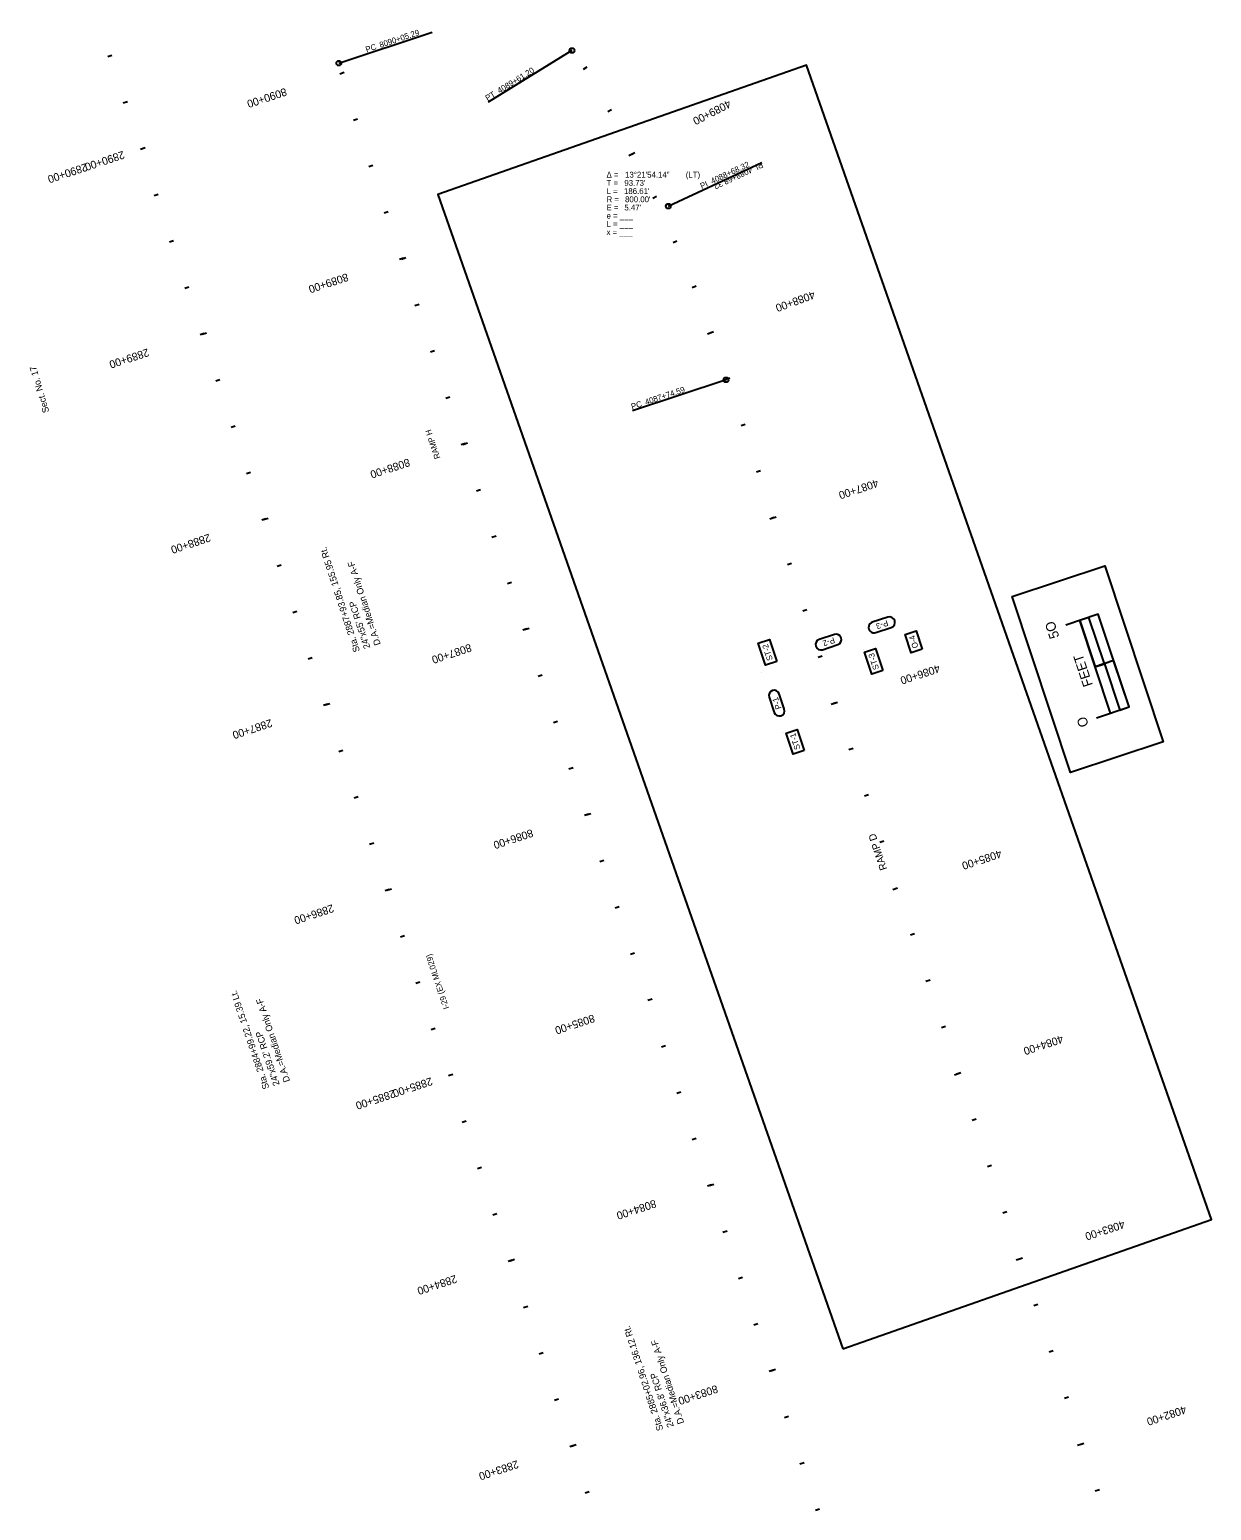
# Model space of a CAD drawing. Extents: x 16395645 to 16399055, y 7230557 to 7240583.
# Drawn here: x 16397055 to 16397660, y 7235571 to 7236330 of the extents above; entities that cross this region are included whole.
import ezdxf

# ---------------------------------------------------------------- set-up
doc = ezdxf.new("R2010")
doc.units = 0
for name, color, linetype in [('Default', 7, 'Continuous'), ('Dimensions', 7, 'Continuous'), ('NamedBoundary', 7, 'Continuous'), ('SheetText', 7, 'Continuous'), ('Text', 7, 'Continuous'), ('TextAlignment', 7, 'Continuous'), ('TextAlignmentLrg', 7, 'Continuous'), ('TextAlignmentSml', 7, 'Continuous')]:
    doc.layers.add(name, color=color, linetype=linetype)

msp = doc.modelspace()

# ---------------------------------------------------------------- linework, layer by layer
at = {"layer": 'Default'}
for p, q in [((16397481.85, 7236012.31), (16397481.85, 7236012.31)), ((16397429.88, 7236000.63), (16397429.88, 7236000.63)), ((16397440.65, 7235969.43), (16397440.65, 7235969.43))]:
    msp.add_line(p, q, dxfattribs=at)
at = {"layer": 'Dimensions'}
for p, q in [((16397494.46, 7236028.78), (16397486.54, 7236026.15)), ((16397467.16, 7236019.93), (16397459.32, 7236017.32)), ((16397488.29, 7236020.87), (16397496.21, 7236023.5)), ((16397461.06, 7236012.1), (16397468.9, 7236014.71)), ((16397441.47, 7235981.72), (16397438.9, 7235989.46)), ((16397433.72, 7235987.74), (16397436.29, 7235980))]:
    msp.add_line(p, q, dxfattribs=at)
for points in [[(16397512.09, 7236012.43), (16397506.4, 7236010.54), (16397503.31, 7236019.82), (16397509, 7236021.71)], [(16397437.57, 7236006.08), (16397431.88, 7236004.19), (16397428.14, 7236015.44), (16397433.83, 7236017.33)], [(16397491.93, 7236001.41), (16397486.23, 7235999.52), (16397482.48, 7236010.81), (16397488.18, 7236012.7)], [(16397451.65, 7235960.48), (16397445.96, 7235958.58), (16397442.39, 7235969.32), (16397448.09, 7235971.21)]]:
    msp.add_lwpolyline(points, close=True, dxfattribs=at)
for centre, radius, start, end in [((16397495.34, 7236026.14), 2.78, 288.38009, 108.38009), ((16397468.03, 7236017.32), 2.75, 288.38195, 108.38195), ((16397487.42, 7236023.51), 2.78, 108.38009, 288.38009), ((16397460.19, 7236014.71), 2.75, 108.38195, 288.38195), ((16397436.31, 7235988.6), 2.73, 18.38195, 198.38195), ((16397438.88, 7235980.86), 2.73, 198.38195, 18.38195)]:
    msp.add_arc(centre, radius, start, end, dxfattribs=at)
at = {"layer": 'NamedBoundary'}
msp.add_lwpolyline([(16397471.39, 7235654.1), (16397660.13, 7235720.26), (16397452.89, 7236311.41), (16397264.15, 7236245.24)], close=True, dxfattribs=at)
at = {"layer": 'SheetText'}
msp.add_line((16397610.1, 7236006.51), (16397600.61, 7236003.35), dxfattribs=at)
msp.add_line((16397610.1, 7236006.51), (16397600.61, 7236003.35), dxfattribs=at)
for points in [[(16397588.07, 7235949.13), (16397558.11, 7236039.28), (16397605.56, 7236055.05), (16397635.52, 7235964.9)], [(16397588.07, 7235949.13), (16397558.11, 7236039.28), (16397605.56, 7236055.05), (16397635.52, 7235964.9)], [(16397635.52, 7235964.9), (16397588.07, 7235949.13), (16397558.11, 7236039.28), (16397605.56, 7236055.05)], [(16397605.33, 7236004.92), (16397597.44, 7236028.64), (16397592.73, 7236027.08), (16397600.61, 7236003.35)], [(16397617.99, 7235982.78), (16397610.1, 7236006.51), (16397605.33, 7236004.92), (16397613.21, 7235981.19)]]:
    msp.add_lwpolyline(points, close=True, dxfattribs=at)
for points in [[(16397601.38, 7235977.26), (16397617.99, 7235982.78), (16397602.22, 7236030.23), (16397585.61, 7236024.71)], [(16397608.5, 7235979.63), (16397592.73, 7236027.08)]]:
    msp.add_lwpolyline(points, dxfattribs=at)
at = {"layer": 'TextAlignment'}
for p, q in [((16397213.38, 7236312.46), (16397261.21, 7236328.35)), ((16397261.21, 7236328.35), (16397261.21, 7236328.35)), ((16397332.76, 7236318.95), (16397289.9, 7236292.43)), ((16397289.9, 7236292.43), (16397289.9, 7236292.43)), ((16397382.08, 7236239.24), (16397429.9, 7236261.61)), ((16397382.08, 7236239.24), (16397429.9, 7236261.61)), ((16397429.9, 7236261.61), (16397429.9, 7236261.61)), ((16397429.9, 7236261.61), (16397429.9, 7236261.61)), ((16397411.63, 7236150.29), (16397363.81, 7236134.4)), ((16397363.81, 7236134.4), (16397363.81, 7236134.4))]:
    msp.add_line(p, q, dxfattribs=at)
for centre in [(16397332.76, 7236318.95), (16397213.38, 7236312.46), (16397382.08, 7236239.24), (16397382.08, 7236239.24), (16397411.63, 7236150.29)]:
    msp.add_circle(centre, 1.25, dxfattribs=at)
at = {"layer": 'TextAlignmentLrg'}
for p, q in [((16397213.88, 7236307.05), (16397216.21, 7236307.83)), ((16397111.84, 7236268.5), (16397114.16, 7236269.27)), ((16397362.94, 7236265.72), (16397364.88, 7236266.73)), ((16397246.58, 7236212.54), (16397244.51, 7236211.85)), ((16397144.53, 7236173.98), (16397142.46, 7236173.3)), ((16397403.24, 7236174.28), (16397405.29, 7236175.03)), ((16397278.12, 7236117.65), (16397276.04, 7236116.96)), ((16397435.16, 7236079.51), (16397437.23, 7236080.2)), ((16397176.07, 7236079.09), (16397174, 7236078.4)), ((16397309.65, 7236022.75), (16397307.58, 7236022.06)), ((16397207.6, 7235984.19), (16397205.53, 7235983.5)), ((16397466.69, 7235984.61), (16397468.76, 7235985.3)), ((16397341.19, 7235927.85), (16397339.11, 7235927.16)), ((16397497.06, 7235889.33), (16397499.39, 7235890.1)), ((16397239.14, 7235889.29), (16397237.07, 7235888.6)), ((16397371.56, 7235832.57), (16397373.88, 7235833.34)), ((16397269.51, 7235794.01), (16397271.83, 7235794.78)), ((16397529.76, 7235794.82), (16397531.83, 7235795.51)), ((16397404.26, 7235738.06), (16397402.18, 7235737.37)), ((16397561.3, 7235699.92), (16397563.37, 7235700.61)), ((16397302.21, 7235699.5), (16397300.14, 7235698.81)), ((16397435.79, 7235643.16), (16397433.72, 7235642.47)), ((16397333.74, 7235604.6), (16397331.67, 7235603.91)), ((16397592.83, 7235605.02), (16397594.9, 7235605.71))]:
    msp.add_line(p, q, dxfattribs=at)
at = {"layer": 'TextAlignmentSml'}
for p, q in [((16397097.23, 7236316.33), (16397095.16, 7236315.64)), ((16397213.88, 7236307.05), (16397216.21, 7236307.83)), ((16397338.58, 7236309.38), (16397340.46, 7236310.51)), ((16397105.11, 7236292.61), (16397103.04, 7236291.92)), ((16397351.1, 7236287.74), (16397353.01, 7236288.81)), ((16397222.93, 7236283.72), (16397220.86, 7236283.03)), ((16397111.84, 7236268.5), (16397114.16, 7236269.27)), ((16397361.85, 7236265.16), (16397364.02, 7236266.29)), ((16397230.81, 7236259.99), (16397228.74, 7236259.3)), ((16397120.88, 7236245.16), (16397118.81, 7236244.47)), ((16397374.08, 7236243.35), (16397376.05, 7236244.29)), ((16397238.7, 7236236.27), (16397236.62, 7236235.58)), ((16397128.77, 7236221.43), (16397126.69, 7236220.74)), ((16397384.52, 7236220.63), (16397386.52, 7236221.51)), ((16397245.42, 7236212.16), (16397247.74, 7236212.93)), ((16397136.65, 7236197.71), (16397134.58, 7236197.02)), ((16397394.24, 7236197.6), (16397396.27, 7236198.42)), ((16397254.46, 7236188.82), (16397252.39, 7236188.13)), ((16397143.37, 7236173.6), (16397145.69, 7236174.37)), ((16397402.09, 7236173.85), (16397404.39, 7236174.7)), ((16397262.35, 7236165.09), (16397260.28, 7236164.41)), ((16397152.42, 7236150.26), (16397150.34, 7236149.57)), ((16397411.5, 7236150.68), (16397413.58, 7236151.37)), ((16397270.23, 7236141.37), (16397268.16, 7236140.68)), ((16397160.3, 7236126.54), (16397158.23, 7236125.85)), ((16397419.39, 7236126.96), (16397421.46, 7236127.65)), ((16397276.95, 7236117.26), (16397279.28, 7236118.03)), ((16397168.18, 7236102.81), (16397166.11, 7236102.12)), ((16397427.27, 7236103.23), (16397429.34, 7236103.92)), ((16397286, 7236093.92), (16397283.93, 7236093.23)), ((16397174.91, 7236078.7), (16397177.23, 7236079.47)), ((16397433.99, 7236079.12), (16397436.32, 7236079.9)), ((16397293.88, 7236070.2), (16397291.81, 7236069.51)), ((16397183.95, 7236055.36), (16397181.88, 7236054.67)), ((16397443.04, 7236055.78), (16397445.11, 7236056.47)), ((16397301.77, 7236046.47), (16397299.69, 7236045.78)), ((16397191.84, 7236031.64), (16397189.76, 7236030.95)), ((16397450.92, 7236032.06), (16397453, 7236032.75)), ((16397308.49, 7236022.36), (16397310.81, 7236023.13)), ((16397199.72, 7236007.91), (16397197.65, 7236007.23)), ((16397458.81, 7236008.34), (16397460.88, 7236009.02)), ((16397317.53, 7235999.02), (16397315.46, 7235998.33)), ((16397206.44, 7235983.8), (16397208.76, 7235984.58)), ((16397465.53, 7235984.23), (16397467.85, 7235985)), ((16397325.42, 7235975.3), (16397323.35, 7235974.61)), ((16397215.49, 7235960.47), (16397213.41, 7235959.78)), ((16397474.57, 7235960.89), (16397476.65, 7235961.58)), ((16397333.3, 7235951.57), (16397331.23, 7235950.89)), ((16397223.37, 7235936.74), (16397221.3, 7235936.05)), ((16397482.46, 7235937.16), (16397484.53, 7235937.85)), ((16397340.02, 7235927.46), (16397342.35, 7235928.24)), ((16397231.25, 7235913.02), (16397229.18, 7235912.33)), ((16397490.34, 7235913.44), (16397492.41, 7235914.13)), ((16397349.07, 7235904.13), (16397347, 7235903.44)), ((16397237.98, 7235888.91), (16397240.3, 7235889.68)), ((16397497.06, 7235889.33), (16397499.39, 7235890.1)), ((16397356.95, 7235880.4), (16397354.88, 7235879.71)), ((16397247.02, 7235865.57), (16397244.95, 7235864.88)), ((16397506.11, 7235865.99), (16397508.18, 7235866.68)), ((16397364.84, 7235856.68), (16397362.76, 7235855.99)), ((16397254.91, 7235841.84), (16397252.83, 7235841.15)), ((16397513.99, 7235842.27), (16397516.07, 7235842.95)), ((16397371.56, 7235832.57), (16397373.88, 7235833.34)), ((16397262.79, 7235818.12), (16397260.72, 7235817.43)), ((16397521.88, 7235818.54), (16397523.95, 7235819.23)), ((16397380.6, 7235809.23), (16397378.53, 7235808.54)), ((16397269.51, 7235794.01), (16397271.83, 7235794.78)), ((16397528.6, 7235794.43), (16397530.92, 7235795.2)), ((16397388.49, 7235785.5), (16397386.42, 7235784.82)), ((16397278.56, 7235770.67), (16397276.48, 7235769.98)), ((16397537.64, 7235771.09), (16397539.72, 7235771.78)), ((16397396.37, 7235761.78), (16397394.3, 7235761.09)), ((16397286.44, 7235746.95), (16397284.37, 7235746.26)), ((16397545.53, 7235747.37), (16397547.6, 7235748.06)), ((16397403.09, 7235737.67), (16397405.42, 7235738.44)), ((16397294.32, 7235723.22), (16397292.25, 7235722.53)), ((16397553.41, 7235723.64), (16397555.48, 7235724.33)), ((16397412.14, 7235714.33), (16397410.07, 7235713.64)), ((16397560.13, 7235699.53), (16397562.46, 7235700.31)), ((16397301.05, 7235699.11), (16397303.37, 7235699.88)), ((16397420.02, 7235690.61), (16397417.95, 7235689.92)), ((16397310.09, 7235675.77), (16397308.02, 7235675.08)), ((16397569.18, 7235676.19), (16397571.25, 7235676.88)), ((16397427.91, 7235666.88), (16397425.83, 7235666.19)), ((16397317.98, 7235652.05), (16397315.9, 7235651.36)), ((16397577.06, 7235652.47), (16397579.14, 7235653.16)), ((16397434.63, 7235642.77), (16397436.95, 7235643.54)), ((16397325.86, 7235628.32), (16397323.79, 7235627.64)), ((16397584.95, 7235628.75), (16397587.02, 7235629.43)), ((16397443.67, 7235619.43), (16397441.6, 7235618.74)), ((16397332.58, 7235604.21), (16397334.9, 7235604.99)), ((16397591.67, 7235604.64), (16397593.99, 7235605.41)), ((16397451.56, 7235595.71), (16397449.49, 7235595.02)), ((16397341.63, 7235580.88), (16397339.55, 7235580.19)), ((16397600.71, 7235581.3), (16397602.79, 7235581.99)), ((16397459.44, 7235571.98), (16397457.37, 7235571.3))]:
    msp.add_line(p, q, dxfattribs=at)

# ---------------------------------------------------------------- texts
at = {"layer": 'Dimensions'}
for s, height, rotation, p in [('RAMP H', 3, 108.38337, (16397265.41, 7236110.34)), ('P-3', 3, 198.38009, (16397494.06, 7236027.32)), ('P-2', 3, 198.38195, (16397466.75, 7236018.52)), ('P-1', 3, 108.38195, (16397440.06, 7235982.14)), ('RAMP D', 3.75, 108.38195, (16397494.15, 7235899.81)), ('I-29 (EX ML029)', 3, 108.38337, (16397269.9, 7235828.54))]:
    msp.add_text(s, height=height, rotation=rotation, dxfattribs=at).set_placement(p)
at = {"layer": 'SheetText'}
for s, p in [('5O', (16397582.34, 7236018.69)), ('FEET', (16397599.49, 7235994.06)), ('O', (16397597.41, 7235973.35))]:
    msp.add_text(s, height=5, rotation=108.38195, dxfattribs=at).set_placement(p)
at = {"layer": 'Text'}
for s, height, rotation, p in [('Sect. No. 17', 3.36, 106.2281, (16397065.16, 7236133.93)), ('Sta. 2887+93.85, 155.95 Rt.', 3.36, 107.97206, (16397224.24, 7236011.44)), ('D.A.=Median Only A-F', 3.36, 107.97206, (16397234.89, 7236014.9)), ('24"x55\' RCP', 3.36, 107.97206, (16397229.56, 7236013.17)), ('O-4', 3, 108.38195, (16397510.19, 7236013.38)), ('ST-2', 3, 108.38195, (16397435.68, 7236007.03)), ('ST-3', 3, 108.38195, (16397490.03, 7236002.36)), ('ST-1', 3, 108.38195, (16397449.76, 7235961.43)), ('Sta. 2884+99.22, 15.39 Lt.', 3.36, 108.59542, (16397177.86, 7235787.63)), ('D.A.=Median Only A-F', 3.36, 108.59542, (16397188.47, 7235791.2)), ('24"x59.2\' RCP', 3.36, 108.59542, (16397183.16, 7235789.41)), ('Sta. 2885+02.96, 136.12 Rt.', 3.36, 107.97206, (16397379.59, 7235612.66)), ('D.A.=Median Only A-F', 3.36, 107.97206, (16397390.25, 7235616.11)), ('24"x36.8\' RCP', 3.36, 107.97206, (16397384.92, 7235614.39))]:
    msp.add_text(s, height=height, rotation=rotation, dxfattribs=at).set_placement(p)
at = {"layer": 'TextAlignment'}
for s, rotation, p in [('8090+05.29', 18.38195, (16397234.75, 7236320.26)), ('PC', 18.38195, (16397227.66, 7236317.9)), ('4089+61.20', 31.74699, (16397295.72, 7236296.81)), ('PT', 31.74699, (16397289.55, 7236292.99)), ('4088+68.32', 25.06447, (16397404.65, 7236250.53)), ('PI ', 205.06447, (16397429.72, 7236261.99)), ('4088+68.32', 205.06447, (16397424.31, 7236259.46)), ('PI ', 25.06447, (16397399.24, 7236247.99)), ('4087+74.59', 18.38195, (16397370.69, 7236137.38)), ('PC', 18.38195, (16397363.6, 7236135.02))]:
    msp.add_text(s, height=3, rotation=rotation, dxfattribs=at).set_placement(p)
for s, p in [('Δ = ', (16397350.46, 7236253.85)), ('13°21\'54.14"', (16397359.95, 7236253.85)), (' (LT)', (16397389.9, 7236253.85)), ('T = ', (16397350.46, 7236249.65)), ('L = ', (16397350.46, 7236245.45)), ("186.61'", (16397359.39, 7236245.45)), ("93.73'", (16397359.58, 7236249.65)), ('R = ', (16397350.46, 7236241.25)), ('E = ', (16397350.46, 7236237.05)), ("5.47'", (16397359.58, 7236237.05)), ("800.00'", (16397359.94, 7236241.25)), ('e = ___ ', (16397350.46, 7236232.85)), ('L = ___', (16397350.46, 7236228.65)), ('x = ___', (16397350.46, 7236224.45))]:
    msp.add_text(s, height=3, dxfattribs=at).set_placement(p)
at = {"layer": 'TextAlignmentLrg'}
for s, p in [('8090+00', (16397185.94, 7236299.88)), ('2890+00', (16397102.88, 7236267.63)), ('4085+00', (16397551.97, 7235909.69)), ('8085+00', (16397343.62, 7235825.39)), ('2885+00', (16397260.55, 7235793.14))]:
    msp.add_text(s, height=4.008, rotation=198.38195, dxfattribs=at).set_placement(p)
at = {"layer": 'TextAlignmentSml'}
for s, rotation, p in [('8090+00', 198.38195, (16397185.94, 7236299.88)), ('4089+00', 207.36392, (16397412.91, 7236293.84)), ('2890+00', 198.38195, (16397083.9, 7236261.32)), ('8089+00', 198.38195, (16397217.48, 7236204.98)), ('4088+00', 200.20195, (16397456.33, 7236195.95)), ('2889+00', 198.38195, (16397115.43, 7236166.43)), ('8088+00', 198.38195, (16397249.01, 7236110.09)), ('4087+00', 198.38195, (16397488.9, 7236099.48)), ('2888+00', 198.38195, (16397146.97, 7236071.53)), ('8087+00', 198.38195, (16397280.55, 7236015.19)), ('4086+00', 198.38195, (16397520.44, 7236004.58)), ('2887+00', 198.38195, (16397178.5, 7235976.63)), ('8086+00', 198.38195, (16397312.08, 7235920.29)), ('4085+00', 198.38195, (16397551.97, 7235909.69)), ('2886+00', 198.38195, (16397210.04, 7235881.73)), ('8085+00', 198.38195, (16397343.62, 7235825.39)), ('4084+00', 198.38195, (16397583.51, 7235814.79)), ('2885+00', 198.38195, (16397241.57, 7235786.84)), ('8084+00', 198.38195, (16397375.15, 7235730.5)), ('4083+00', 198.38195, (16397615.04, 7235719.89)), ('2884+00', 198.38195, (16397273.11, 7235691.94)), ('8083+00', 198.38195, (16397406.69, 7235635.6)), ('4082+00', 198.38195, (16397646.58, 7235624.99)), ('2883+00', 198.38195, (16397304.64, 7235597.04))]:
    msp.add_text(s, height=4.008, rotation=rotation, dxfattribs=at).set_placement(p)

doc.saveas('drawing.dxf')
